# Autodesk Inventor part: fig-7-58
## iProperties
Shininess: 77.0
Length Units: 11269
Angle Units: 11279
Time Units: 11290
Mass Units: 11283
Length Display Precision: 3
Angle Display Precision: 2
Created: 2002-01
Part Number: fig-7-58
Document SubType Name: Modeling
Designer: ***
Density: 1 g/cm^3
Density: 0.0
Volumn: 0.0
Area: 0.0
PropertySet Name: Model Information
Control State: 0
Master: False
Checked Out: False
Author: ***
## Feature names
1. Sweep1
2. Split5
